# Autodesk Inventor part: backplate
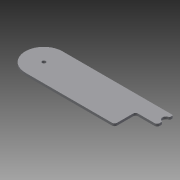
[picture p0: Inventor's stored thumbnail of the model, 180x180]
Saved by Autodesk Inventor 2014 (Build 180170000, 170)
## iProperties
Created: 2015-01
Part Number: backplate
Material: Generic
Document SubType Name: Modeling
Designer: Drano
Density: 1 g/cm^3
Appearance: Default
Author: Drano
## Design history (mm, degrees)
sketch "Sketch1"
  geometry: L1 (-29.936, -17.777)-(42.564, -17.777); L2 (-29.936, 13.223)-(47.064, 13.223); L3 (47.064, 13.223)-(61.564, 13.223); L4 (62.564, 1.723)-(62.564, 3.35); L5 (62.564, 11.096)-(62.564, 12.223); L6 (46.564, -0.277)-(60.564, -0.277); L7 (44.564, -15.777)-(44.564, -2.277); C1 r 1.5 at (-29.936, -2.277); A1 r 2 centre (42.564, -15.777) between (42.564, -17.777) and (44.564, -15.777); A2 r 15.5 centre (-29.936, -2.277) between (-29.936, 13.223) and (-29.936, -17.777); A3 r 1 centre (61.564, 12.223) between (62.564, 12.223) and (61.564, 13.223); A4 r 2 centre (60.564, 1.723) between (60.564, -0.277) and (62.564, 1.723); A5 r 3 centre (62.564, 7.223) between (61.814, 10.127) and (61.814, 4.318); A6 r 1 centre (61.564, 3.35) between (62.564, 3.35) and (61.814, 4.318); A7 r 1 centre (61.564, 11.096) between (61.814, 10.127) and (62.564, 11.096); A8 r 2 centre (46.564, -2.277) between (46.564, -0.277) and (44.564, -2.277); 1 further point
  constraints: 16 point on circle, 14 end point, 9 centre point
extrude "Extrusion1" new body sketch "Sketch1" distance "d0" = 2; taper "d1" = 0 deg
body "Solid1"
